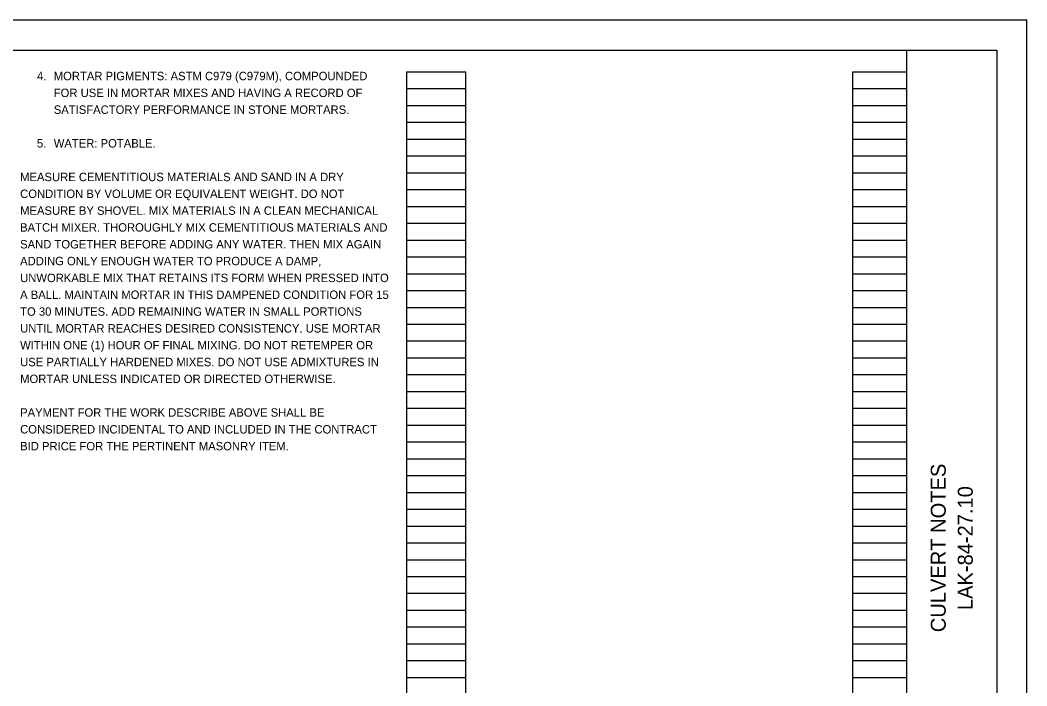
# Model space of a CAD drawing. Extents: x 0 to 63.6, y 0 to 22.
# Drawn here: x 17.24 to 34, y 10.92 to 22 of the extents above; entities that cross this region are included whole.
import ezdxf

# ---------------------------------------------------------------- set-up
doc = ezdxf.new("R2010")
doc.units = 0
for name, color, linetype in [('SH_Border', 7, 'Continuous'), ('SH_Cut_Line', 7, 'Continuous'), ('SH_Data', 7, 'Continuous'), ('SH_Text', 7, 'Continuous')]:
    doc.layers.add(name, color=color, linetype=linetype)

msp = doc.modelspace()

# ---------------------------------------------------------------- linework, layer by layer
at = {"layer": 'SH_Border'}
msp.add_line((32, 0.5), (32, 21.5), dxfattribs=at)
msp.add_lwpolyline([(1.5, 21.5), (33.5, 21.5), (33.5, 0.5), (1.5, 0.5)], close=True, dxfattribs=at)
at = {"layer": 'SH_Cut_Line'}
msp.add_lwpolyline([(0, 0), (34, 0), (34, 22), (0, 22)], close=True, dxfattribs=at)
at = {"layer": 'SH_Data'}
for p, q in [((23.68, 0.98), (23.68, 21.14)), ((23.68, 21.14), (24.66, 21.14)), ((24.66, 0.98), (24.66, 21.14)), ((31.1, 0.98), (31.1, 21.14)), ((31.1, 21.14), (32, 21.14)), ((32, 0.98), (32, 21.14)), ((23.68, 20.86), (24.66, 20.86)), ((31.1, 20.86), (32, 20.86)), ((23.68, 20.58), (24.66, 20.58)), ((31.1, 20.58), (32, 20.58)), ((23.68, 20.3), (24.66, 20.3)), ((31.1, 20.3), (32, 20.3)), ((23.68, 20.02), (24.66, 20.02)), ((31.1, 20.02), (32, 20.02)), ((23.68, 19.74), (24.66, 19.74)), ((31.1, 19.74), (32, 19.74)), ((23.68, 19.46), (24.66, 19.46)), ((31.1, 19.46), (32, 19.46)), ((23.68, 19.18), (24.66, 19.18)), ((31.1, 19.18), (32, 19.18)), ((23.68, 18.9), (24.66, 18.9)), ((31.1, 18.9), (32, 18.9)), ((23.68, 18.62), (24.66, 18.62)), ((31.1, 18.62), (32, 18.62)), ((23.68, 18.34), (24.66, 18.34)), ((31.1, 18.34), (32, 18.34)), ((23.68, 18.06), (24.66, 18.06)), ((31.1, 18.06), (32, 18.06)), ((23.68, 17.78), (24.66, 17.78)), ((31.1, 17.78), (32, 17.78)), ((23.68, 17.5), (24.66, 17.5)), ((31.1, 17.5), (32, 17.5)), ((23.68, 17.22), (24.66, 17.22)), ((31.1, 17.22), (32, 17.22)), ((23.68, 16.94), (24.66, 16.94)), ((31.1, 16.94), (32, 16.94)), ((23.68, 16.66), (24.66, 16.66)), ((31.1, 16.66), (32, 16.66)), ((23.68, 16.38), (24.66, 16.38)), ((31.1, 16.38), (32, 16.38)), ((23.68, 16.1), (24.66, 16.1)), ((31.1, 16.1), (32, 16.1)), ((23.68, 15.82), (24.66, 15.82)), ((31.1, 15.82), (32, 15.82)), ((23.68, 15.54), (24.66, 15.54)), ((31.1, 15.54), (32, 15.54)), ((23.68, 15.26), (24.66, 15.26)), ((31.1, 15.26), (32, 15.26)), ((23.68, 14.98), (24.66, 14.98)), ((31.1, 14.98), (32, 14.98)), ((23.68, 14.7), (24.66, 14.7)), ((31.1, 14.7), (32, 14.7)), ((23.68, 14.42), (24.66, 14.42)), ((31.1, 14.42), (32, 14.42)), ((23.68, 14.14), (24.66, 14.14)), ((31.1, 14.14), (32, 14.14)), ((23.68, 13.86), (24.66, 13.86)), ((31.1, 13.86), (32, 13.86)), ((23.68, 13.58), (24.66, 13.58)), ((31.1, 13.58), (32, 13.58)), ((23.68, 13.3), (24.66, 13.3)), ((31.1, 13.3), (32, 13.3)), ((23.68, 13.02), (24.66, 13.02)), ((31.1, 13.02), (32, 13.02)), ((23.68, 12.74), (24.66, 12.74)), ((31.1, 12.74), (32, 12.74)), ((23.68, 12.46), (24.66, 12.46)), ((31.1, 12.46), (32, 12.46)), ((23.68, 12.18), (24.66, 12.18)), ((31.1, 12.18), (32, 12.18)), ((23.68, 11.9), (24.66, 11.9)), ((31.1, 11.9), (32, 11.9)), ((23.68, 11.62), (24.66, 11.62)), ((31.1, 11.62), (32, 11.62)), ((23.68, 11.34), (24.66, 11.34)), ((31.1, 11.34), (32, 11.34)), ((23.68, 11.06), (24.66, 11.06)), ((31.1, 11.06), (32, 11.06))]:
    msp.add_line(p, q, dxfattribs=at)

# ---------------------------------------------------------------- texts
for s, p in [('CULVERT NOTES', (32.65, 11.813)), ('LAK-84-27.10', (33.1, 12.181))]:
    msp.add_text(s, height=0.25, rotation=90, dxfattribs=at).set_placement(p)
at = {"layer": 'SH_Text'}
for s, p in [('4.', (17.52, 21)), ('MORTAR PIGMENTS: ASTM C979 (C979M), COMPOUNDED ', (17.8, 21)), ('FOR USE IN MORTAR MIXES AND HAVING A RECORD OF ', (17.8, 20.72)), ('SATISFACTORY PERFORMANCE IN STONE MORTARS.', (17.8, 20.44)), ('5.', (17.52, 19.88)), ('WATER: POTABLE.', (17.8, 19.88)), ('MEASURE CEMENTITIOUS MATERIALS AND SAND IN A DRY ', (17.24, 19.32)), ('CONDITION BY VOLUME OR EQUIVALENT WEIGHT. DO NOT ', (17.24, 19.04)), ('MEASURE BY SHOVEL. MIX MATERIALS IN A CLEAN MECHANICAL ', (17.24, 18.76)), ('BATCH MIXER. THOROUGHLY MIX CEMENTITIOUS MATERIALS AND ', (17.24, 18.48)), ('SAND TOGETHER BEFORE ADDING ANY WATER. THEN MIX AGAIN ', (17.24, 18.2)), ('ADDING ONLY ENOUGH WATER TO PRODUCE A DAMP, ', (17.24, 17.92)), ('UNWORKABLE MIX THAT RETAINS ITS FORM WHEN PRESSED INTO ', (17.24, 17.64)), ('A BALL. MAINTAIN MORTAR IN THIS DAMPENED CONDITION FOR 15 ', (17.24, 17.36)), ('TO 30 MINUTES. ADD REMAINING WATER IN SMALL PORTIONS ', (17.24, 17.08)), ('UNTIL MORTAR REACHES DESIRED CONSISTENCY. USE MORTAR ', (17.24, 16.8)), ('WITHIN ONE (1) HOUR OF FINAL MIXING. DO NOT RETEMPER OR ', (17.24, 16.52)), ('USE PARTIALLY HARDENED MIXES. DO NOT USE ADMIXTURES IN ', (17.24, 16.24)), ('MORTAR UNLESS INDICATED OR DIRECTED OTHERWISE.', (17.24, 15.96)), ('PAYMENT FOR THE WORK DESCRIBE ABOVE SHALL BE ', (17.24, 15.4)), ('CONSIDERED INCIDENTAL TO AND INCLUDED IN THE CONTRACT ', (17.24, 15.12)), ('BID PRICE FOR THE PERTINENT MASONRY ITEM.', (17.24, 14.84))]:
    msp.add_text(s, height=0.14, rotation=360, dxfattribs=at).set_placement(p)

doc.saveas('drawing.dxf')
